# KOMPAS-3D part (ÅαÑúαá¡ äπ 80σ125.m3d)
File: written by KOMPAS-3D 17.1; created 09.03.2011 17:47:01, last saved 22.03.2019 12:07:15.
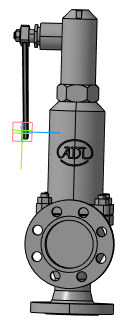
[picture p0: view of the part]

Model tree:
1. Плоскость XY
2. Плоскость ZX
3. Плоскость ZY
4. Ось X
5. Ось Y
6. Ось Z
7. Начало координат
8. Операция без истории:2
